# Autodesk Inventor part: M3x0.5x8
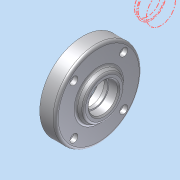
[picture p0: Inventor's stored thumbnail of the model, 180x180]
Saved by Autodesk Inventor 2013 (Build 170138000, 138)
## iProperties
Company: 한국ATC센터
Created: 2009-02
Part Number: M3x0.5x8
Document SubType Name: Modeling
Designer: KYOUNG IL JANG
Density: 2.71 g/cm^3
Mass: 97.9591 g
Surface Area: 115.525 cm^2
Volume: 36.1473 cm^3
Material: 알루미늄-6061
Vendor: CBT Solutions
Author: KYOUNG IL JANG
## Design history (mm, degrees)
sketch "스케치1"
  geometry: L1 (-10.5, 0)-(10.5, 0); L2 (10.5, 0)-(10.5, 22.5); L3 (10.5, 22.5)-(5.5, 22.5); L4 (5.5, 22.5)-(5.5, 32.5); L5 (5.5, 32.5)-(-6.5, 32.5); L6 (-6.5, 32.5)-(-6.5, 17.5); L7 (-6.5, 17.5)-(-10.5, 15.191); L8 (-10.5, 15.191)-(-10.5, 0); 2 further points
  constraints: 16 end point, 3 parallel, 3 perpendicular, 1 coincident, 1 horizontal, 1 midpoint
  dimensions: "d0" = 21 distance of L1.start L1.end; "d1" = 65 diameter of L5 L1; "d2" = 45 diameter of L3 L1; "d3" = 35 diameter of L6.end L1; "d4" = 120 deg angle of L7 L6; "d5" = 12 distance of L4.end L5.end; "d6" = 5 distance of L2.end L3.end
revolve "회전1" sketch "스케치1" stored, may be unused: angle "d7" = 90 deg
sketch "스케치2"
  geometry: L1 (0, 0)-(32.5, 0); L2 (0, 0)-(18.738, 18.738); 1 further point
  constraints: 4 end point, 1 horizontal, 1 horizontal alignment, 1 other
  dimensions: "d8" = 45 deg angle of L1 L2; "d9" = 26.5 distance of L1.start L2.end
hole "구멍1" sketch "스케치2" at (18.738, 18.738) diameter "d10" = 3.4; stored, may be unused: countersink angle "d14" = 90 deg, drill point angle "d16" = 118 deg; dims "d11" = 6, "d12" = 6, "d13" = 3.3, "d15" = 8
fillet "모깎기1" dims "d20" = 2
hole "구멍2" diameter "d23" = 15; stored, may be unused: countersink angle "d27" = 90 deg, drill point angle "d29" = 0 deg; dims "d21" = 10, "d22" = 10, "d24" = 6, "d25" = 35, "d26" = 11, "d28" = 14
chamfer "모따기1" distance "d39" = 1; stored, may be unused: second distance "d40" = 2, angle "d41" = 45 deg
fillet "모깎기2" dims "d42" = 0.3
hole "구멍4" diameter "d46" = 17; stored, may be unused: countersink angle "d50" = 90 deg, drill point angle "d52" = 118 deg; dims "d44" = 10, "d45" = 10, "d47" = 6, "d48" = 22, "d49" = 7.3, "d51" = 8
chamfer "모따기2" distance "d53" = 1; stored, may be unused: second distance "d54" = 2, angle "d55" = 45 deg
fillet "모깎기3" dims "d56" = 0.3
node "솔리드1"
pattern_circular "원형 패턴1" dims angle "d18" = 360 deg
